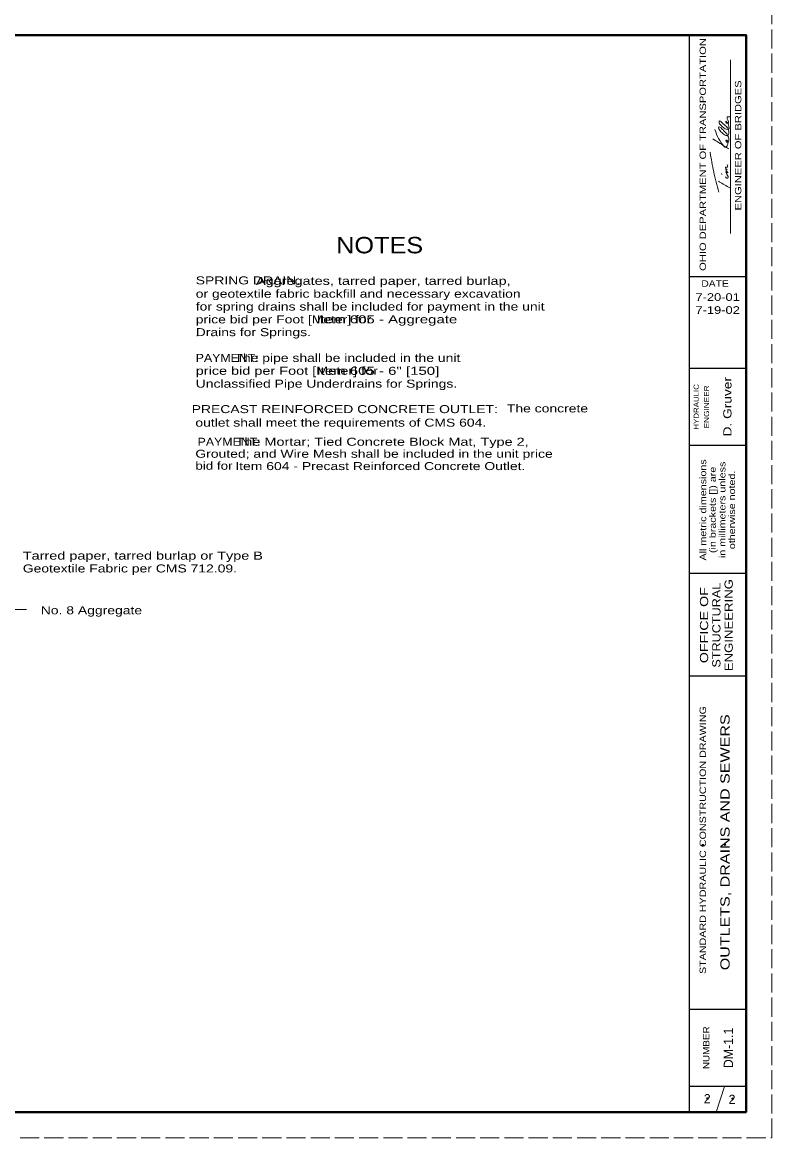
# Model space of a CAD drawing. Extents: x 1083.1 to 1117.1, y 697.4 to 741.4.
# Drawn here: x 1102.52 to 1117.13, y 697.35 to 719.1 of the extents above; entities that cross this region are included whole.
import ezdxf
from ezdxf.enums import TextEntityAlignment as Align

# ---------------------------------------------------------------- set-up
doc = ezdxf.new("R2010")
doc.units = 0
doc.header["$LTSCALE"] = 0.062
doc.header["$PDMODE"] = 32
doc.header["$PDSIZE"] = 0.031
doc.linetypes.add('LONG_DASHED', pattern=[7.5, 6, -1.5])
doc.layers.add('1', color=7, linetype='Continuous', lineweight=13)

msp = doc.modelspace()

# ---------------------------------------------------------------- linework, layer by layer
at = {"layer": '1', "lineweight": 25}
for p, q in [((1085.12642, 718.85408), (1116.62642, 718.85408)), ((1115.52642, 697.85408), (1115.52642, 718.85408)), ((1116.62642, 718.85408), (1116.62642, 697.85408)), ((1116.62642, 714.13825), (1115.52642, 714.13825)), ((1116.62642, 712.35408), (1115.52642, 712.35408)), ((1116.62642, 710.85408), (1115.52642, 710.85408)), ((1116.62642, 708.35408), (1115.52642, 708.35408)), ((1116.62642, 706.35408), (1115.52642, 706.35408)), ((1116.62642, 699.85408), (1115.52642, 699.85408)), ((1116.62642, 698.35408), (1115.52642, 698.35408))]:
    msp.add_line(p, q, dxfattribs=at)
at = {"layer": '1'}
for p, q in [((1116.32517, 714.98508), (1116.32517, 718.37517)), ((1116.15767, 716.136), (1116.1475, 716.15525)), ((1116.04308, 697.85408), (1116.20975, 698.35408))]:
    msp.add_line(p, q, dxfattribs=at)
at = {"layer": '1', "linetype": 'LONG_DASHED'}
msp.add_lwpolyline([(1083.12642, 697.35408), (1117.12642, 697.35408), (1117.12642, 719.35408), (1083.12642, 719.35408)], close=True, dxfattribs=at)
at = {"layer": '1', "lineweight": 25}
msp.add_lwpolyline([(1116.62642, 697.85408), (1085.12642, 697.85408), (1085.12642, 718.85408)], dxfattribs=at)
at = {"layer": '1', "lineweight": 40}
msp.add_lwpolyline([(1085.12642, 718.85408), (1116.62642, 718.85408), (1116.62642, 697.85408), (1085.12642, 697.85408)], close=True, dxfattribs=at)
msp.add_lwpolyline([(1085.12642, 718.85408), (1116.62642, 718.85408), (1116.62642, 697.85408), (1085.12642, 697.85408)], close=True, dxfattribs=at)
at = {"layer": '1'}
msp.add_lwpolyline([(1100.01742, 706.42642), (1102.17033, 707.65183), (1102.60283, 707.65183)], dxfattribs=at)
for points in [[(1116.01825, 717.01108), (1116.20142, 716.68275), (1116.21658, 716.67217), (1116.22675, 716.67217), (1116.25867, 716.69583), (1116.27375, 716.73), (1116.26875, 716.78125), (1116.25183, 716.80308), (1116.23833, 716.80308), (1116.23658, 716.79008), (1116.24675, 716.77492), (1116.26025, 716.7665), (1116.27533, 716.7665), (1116.2905, 716.78808), (1116.29392, 716.80742), (1116.28367, 716.86275), (1116.20142, 716.98317), (1116.15592, 717.02783), (1116.119, 717.06242), (1116.09383, 717.06458), (1116.09558, 717.026), (1116.12075, 716.98725), (1116.188, 716.92492), (1116.23008, 716.8995), (1116.26375, 716.895), (1116.28708, 716.921), (1116.29392, 716.95517), (1116.28883, 716.98092), (1116.25867, 717.05408), (1116.22842, 717.08608), (1116.16783, 717.1395), (1116.13917, 717.16533), (1116.10567, 717.18058), (1116.10225, 717.15258), (1116.11233, 717.12675), (1116.1695, 717.06683), (1116.24017, 717.01958), (1116.29217, 717.02192), (1116.2905, 717.07958), (1116.27867, 717.1225), (1116.26533, 717.14825), (1116.25517, 717.159), (1116.23175, 717.174), (1116.2335, 717.15692), (1116.26875, 717.13542), (1116.28367, 717.14617), (1116.27058, 717.19983), (1116.262, 717.22775), (1116.25867, 717.24042), (1116.25867, 717.25325), (1116.25867, 717.26192), (1116.28367, 717.25975), (1116.30908, 717.25975)], [(1115.97942, 716.82883), (1116.20317, 716.69133), (1116.28883, 716.63567)], [(1116.09567, 715.79183), (1115.997, 716.18708), (1115.92575, 716.56942)], [(1116.22675, 716.09075), (1116.235, 716.08008), (1116.27217, 716.06717), (1116.27692, 716.09958), (1116.25183, 716.136), (1116.23658, 716.17225), (1116.23658, 716.1915), (1116.25183, 716.18525), (1116.262, 716.17442), (1116.27217, 716.17008), (1116.2485, 716.20225), (1116.23658, 716.21725), (1116.2335, 716.23458), (1116.25692, 716.228), (1116.2485, 716.23667), (1116.22333, 716.2645), (1116.2335, 716.27967), (1116.25025, 716.28167), (1116.25867, 716.27967), (1116.26875, 716.301), (1116.262, 716.32892)], [(1116.31083, 715.87625), (1116.10567, 715.99625), (1116.09008, 716.00667)]]:
    msp.add_spline(points, degree=3, dxfattribs=at)
for p in [(1115.78383, 703.06008), (1116.21667, 703.06742), (1115.8745, 698.11783), (1116.36292, 698.11683)]:
    msp.add_point(p, dxfattribs=at)

# ---------------------------------------------------------------- texts
for s, height, width, p in [('OHIO DEPARTMENT OF TRANSPORTATION', 0.125, 1.3, (1115.84633, 716.52633)), ('ENGINEER OF BRIDGES', 0.125, 1.3, (1116.53467, 716.70312)), ('D. Gruver', 0.16, 1.25, (1116.34283, 711.60825)), ('HYDRAULIC', 0.1, 1.15, (1115.7055, 711.60517)), ('ENGINEER', 0.1, 1.2, (1115.90642, 711.60521)), ('All metric dimensions', 0.125, 1.25, (1115.85025, 709.59617)), ('(in brackets []) are', 0.125, 1.25, (1116.03775, 709.59617)), ('in millimeters unless', 0.125, 1.25, (1116.22525, 709.59621)), ('otherwise noted.', 0.125, 1.25, (1116.41275, 709.59617)), ('ENGINEERING', 0.16, 1.2, (1116.36817, 707.34862)), ('OFFICE OF', 0.16, 1.3, (1115.88817, 707.34854)), ('STRUCTURAL', 0.16, 1.15, (1116.12817, 707.34854)), ('STANDARD HYDRAULIC CONSTRUCTION DRAWING', 0.125, 1.25, (1115.84633, 703.15812)), ('OUTLETS, DRAINS AND SEWERS', 0.18, 1.3, (1116.30683, 703.11421)), ('NUMBER', 0.125, 1.15, (1115.91342, 699.10817))]:
    msp.add_text(s, height=height, rotation=90, dxfattribs=dict(at, width=width)).set_placement(p, align=Align.CENTER)
for s, height, width, p in [('NOTES', 0.32, 1.15, (1109.48612, 714.599)), ('DATE', 0.125, 1.2, (1116.02312, 713.94683)), ('7-20-01', 0.15, 1.25, (1116.07346, 713.67133)), ('7-19-02', 0.15, 1.25, (1116.07346, 713.41825)), ('PRECAST REINFORCED CONCRETE OUTLET:', 0.156, 1.3, (1108.80687, 711.48308)), ('No. 8 Aggregate', 0.156, 1.3, (1103.86983, 707.5605))]:
    msp.add_text(s, height=height, dxfattribs=dict(at, width=width)).set_placement(p, align=Align.CENTER)
for s, width, p in [('SPRING DRAIN:', 1.3, (1105.9025, 713.99333)), ('               Aggregates, tarred paper, tarred burlap, ', 1.35, (1105.9025, 713.98417)), ('or geotextile fabric backfill and necessary excavation ', 1.3, (1105.9025, 713.73375)), ('for spring drains shall be included for payment in the unit ', 1.3, (1105.9025, 713.48333)), ('price bid per Foot [Meter] for', 1.3, (1105.9025, 713.23292)), ('                             Item 605 - Aggregate ', 1.4, (1105.90225, 713.2345)), ('Drains for Springs.', 1.3, (1105.90225, 712.98408)), ('PAYMENT:', 1.15, (1105.9025, 712.48292)), ('          The pipe shall be included in the unit', 1.3, (1105.9025, 712.48167)), ('price bid per Foot [Meter] for ', 1.35, (1105.9025, 712.23125)), ('                             Item 605 - 6" [150] ', 1.4, (1105.9025, 712.22992)), ('Unclassified Pipe Underdrains for Springs.', 1.3, (1105.9025, 711.9795)), ('The concrete', 1.3, (1111.96558, 711.49708)), ('outlet shall meet the requirements of CMS 604.', 1.3, (1105.89508, 711.21967)), ('          The Mortar; Tied Concrete Block Mat, Type 2, ', 1.35, (1105.89508, 710.84692)), ('PAYMENT:', 1.15, (1105.93925, 710.84667)), ('Grouted; and Wire Mesh shall be included in the unit price ', 1.3, (1105.89508, 710.61292)), ('bid for', 1.25, (1105.89508, 710.37892)), ('    Item 604 - Precast Reinforced Concrete Outlet.', 1.3, (1106.37242, 710.37242)), ('Tarred paper, tarred burlap or Type B', 1.35, (1102.5315, 708.62633)), ('Geotextile Fabric per CMS 712.09.', 1.3, (1102.5315, 708.37592))]:
    msp.add_text(s, height=0.156, dxfattribs=dict(at, width=width)).set_placement(p)
msp.add_text('.', height=0.156, dxfattribs=at).set_placement((1105.9025, 712.98117))
msp.add_text('DM-1.1', height=0.18, rotation=90, dxfattribs=at).set_placement((1116.3725, 699.10442), align=Align.CENTER)
for p in [(1115.87088, 698.02417), (1116.35371, 698.01158)]:
    msp.add_text('2', height=0.18, dxfattribs=at).set_placement(p, align=Align.CENTER)

doc.saveas('drawing.dxf')
